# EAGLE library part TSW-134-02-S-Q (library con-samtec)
THROUGH-HOLE .025" SQ POST HEADER Source: Samtec TSW.pdf
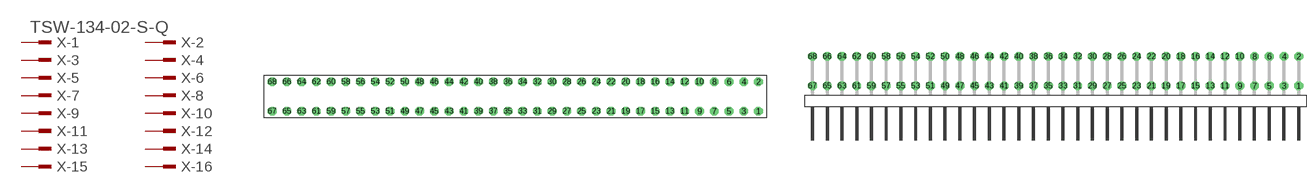
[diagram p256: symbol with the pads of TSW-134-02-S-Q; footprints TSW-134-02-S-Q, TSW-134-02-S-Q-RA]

Designator prefix X; gates -1=MPINV -2=MPIN -3=MPIN -4=MPIN -5=MPIN -6=MPIN -7=MPIN -8=MPIN -9=MPIN -10=MPIN -11=MPIN -12=MPIN -13=MPIN -14=MPIN -15=MPIN -16=MPIN -17=MPIN -18=MPIN -19=MPIN -20=MPIN -21=MPIN -22=MPIN -23=MPIN -24=MPIN -25=MPIN -26=MPIN -27=MPIN -28=MPIN -29=MPIN -30=MPIN -31=MPIN -32=MPIN -33=MPIN -34=MPIN -35=MPIN -36=MPIN -37=MPIN -38=MPIN -39=MPIN -40=MPIN -41=MPIN -42=MPIN -43=MPIN -44=MPIN -45=MPIN -46=MPIN -47=MPIN -48=MPIN -49=MPIN -50=MPIN -51=MPIN -52=MPIN -53=MPIN -54=MPIN -55=MPIN -56=MPIN -57=MPIN -58=MPIN -59=MPIN -60=MPIN -61=MPIN -62=MPIN -63=MPIN -64=MPIN -65=MPIN -66=MPIN -67=MPIN -68=MPIN

## TSW-134-02-S-Q (OC_FARNELL: unknown; OC_NEWARK: unknown)  [TSW-134-02-S-Q]
1  -1:1  pas
2  -2:1  pas
3  -3:1  pas
4  -4:1  pas
5  -5:1  pas
6  -6:1  pas
7  -7:1  pas
8  -8:1  pas
9  -9:1  pas
10  -10:1  pas
11  -11:1  pas
12  -12:1  pas
13  -13:1  pas
14  -14:1  pas
15  -15:1  pas
16  -16:1  pas
17  -17:1  pas
18  -18:1  pas
19  -19:1  pas
20  -20:1  pas
21  -21:1  pas
22  -22:1  pas
23  -23:1  pas
24  -24:1  pas
25  -25:1  pas
26  -26:1  pas
27  -27:1  pas
28  -28:1  pas
29  -29:1  pas
30  -30:1  pas
31  -31:1  pas
32  -32:1  pas
33  -33:1  pas
34  -34:1  pas
35  -35:1  pas
36  -36:1  pas
37  -37:1  pas
38  -38:1  pas
39  -39:1  pas
40  -40:1  pas
41  -41:1  pas
42  -42:1  pas
43  -43:1  pas
44  -44:1  pas
45  -45:1  pas
46  -46:1  pas
47  -47:1  pas
48  -48:1  pas
49  -49:1  pas
50  -50:1  pas
51  -51:1  pas
52  -52:1  pas
53  -53:1  pas
54  -54:1  pas
55  -55:1  pas
56  -56:1  pas
57  -57:1  pas
58  -58:1  pas
59  -59:1  pas
60  -60:1  pas
61  -61:1  pas
62  -62:1  pas
63  -63:1  pas
64  -64:1  pas
65  -65:1  pas
66  -66:1  pas
67  -67:1  pas
68  -68:1  pas

## TSW-134-02-S-Q-RA (OC_FARNELL: unknown; OC_NEWARK: unknown)  [TSW-134-02-S-Q-RA]
Pads as for TSW-134-02-S-Q

## Footprint TSW-134-02-S-Q (pad centres in mm)
THROUGH-HOLE .025" SQ POST HEADER Source: Samtec TSW.pdf
drill 1 pad 1.5 octagon: 1 41.91,-2.54; 2 41.91,2.54; 3 39.37,-2.54; 4 39.37,2.54; 5 36.83,-2.54; 6 36.83,2.54; 7 34.29,-2.54; 8 34.29,2.54; 9 31.75,-2.54; 10 31.75,2.54; 11 29.21,-2.54; 12 29.21,2.54; 13 26.67,-2.54; 14 26.67,2.54; 15 24.13,-2.54; 16 24.13,2.54; 17 21.59,-2.54; 18 21.59,2.54; 19 19.05,-2.54; 20 19.05,2.54; 21 16.51,-2.54; 22 16.51,2.54; 23 13.97,-2.54; 24 13.97,2.54; 25 11.43,-2.54; 26 11.43,2.54; 27 8.89,-2.54; 28 8.89,2.54; 29 6.35,-2.54; 30 6.35,2.54; 31 3.81,-2.54; 32 3.81,2.54; 33 1.27,-2.54; 34 1.27,2.54; 35 -1.27,-2.54; 36 -1.27,2.54; 37 -3.81,-2.54; 38 -3.81,2.54; 39 -6.35,-2.54; 40 -6.35,2.54; 41 -8.89,-2.54; 42 -8.89,2.54; 43 -11.43,-2.54; 44 -11.43,2.54; 45 -13.97,-2.54; 46 -13.97,2.54; 47 -16.51,-2.54; 48 -16.51,2.54; 49 -19.05,-2.54; 50 -19.05,2.54; 51 -21.59,-2.54; 52 -21.59,2.54; 53 -24.13,-2.54; 54 -24.13,2.54; 55 -26.67,-2.54; 56 -26.67,2.54; 57 -29.21,-2.54; 58 -29.21,2.54; 59 -31.75,-2.54; 60 -31.75,2.54; 61 -34.29,-2.54; 62 -34.29,2.54; 63 -36.83,-2.54; 64 -36.83,2.54; 65 -39.37,-2.54; 66 -39.37,2.54; 67 -41.91,-2.54; 68 -41.91,2.54

## Footprint TSW-134-02-S-Q-RA (pad centres in mm)
THROUGH-HOLE .025" SQ POST HEADER Source: Samtec TSW.pdf
drill 1 pad 1.5 octagon: 1 41.91,1.524; 2 41.91,6.604; 3 39.37,1.524; 4 39.37,6.604; 5 36.83,1.524; 6 36.83,6.604; 7 34.29,1.524; 8 34.29,6.604; 9 31.75,1.524; 10 31.75,6.604; 11 29.21,1.524; 12 29.21,6.604; 13 26.67,1.524; 14 26.67,6.604; 15 24.13,1.524; 16 24.13,6.604; 17 21.59,1.524; 18 21.59,6.604; 19 19.05,1.524; 20 19.05,6.604; 21 16.51,1.524; 22 16.51,6.604; 23 13.97,1.524; 24 13.97,6.604; 25 11.43,1.524; 26 11.43,6.604; 27 8.89,1.524; 28 8.89,6.604; 29 6.35,1.524; 30 6.35,6.604; 31 3.81,1.524; 32 3.81,6.604; 33 1.27,1.524; 34 1.27,6.604; 35 -1.27,1.524; 36 -1.27,6.604; 37 -3.81,1.524; 38 -3.81,6.604; 39 -6.35,1.524; 40 -6.35,6.604; 41 -8.89,1.524; 42 -8.89,6.604; 43 -11.43,1.524; 44 -11.43,6.604; 45 -13.97,1.524; 46 -13.97,6.604; 47 -16.51,1.524; 48 -16.51,6.604; 49 -19.05,1.524; 50 -19.05,6.604; 51 -21.59,1.524; 52 -21.59,6.604; 53 -24.13,1.524; 54 -24.13,6.604; 55 -26.67,1.524; 56 -26.67,6.604; 57 -29.21,1.524; 58 -29.21,6.604; 59 -31.75,1.524; 60 -31.75,6.604; 61 -34.29,1.524; 62 -34.29,6.604; 63 -36.83,1.524; 64 -36.83,6.604; 65 -39.37,1.524; 66 -39.37,6.604; 67 -41.91,1.524; 68 -41.91,6.604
